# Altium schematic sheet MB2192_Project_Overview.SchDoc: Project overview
size A4; Date: Not used; ApprovedBy: Not used; CheckedBy: Not used; Author: Not used; CompanyName: STMicroelectronics; DrawnBy: Not used; Engineer: Not used; Organization: Not used; Address1: Not used; Address2: Not used; Address3: Not used; Address4: Not used; DocumentNumber: 1; Revision: Not used; SheetNumber: 1; SheetTotal: 17
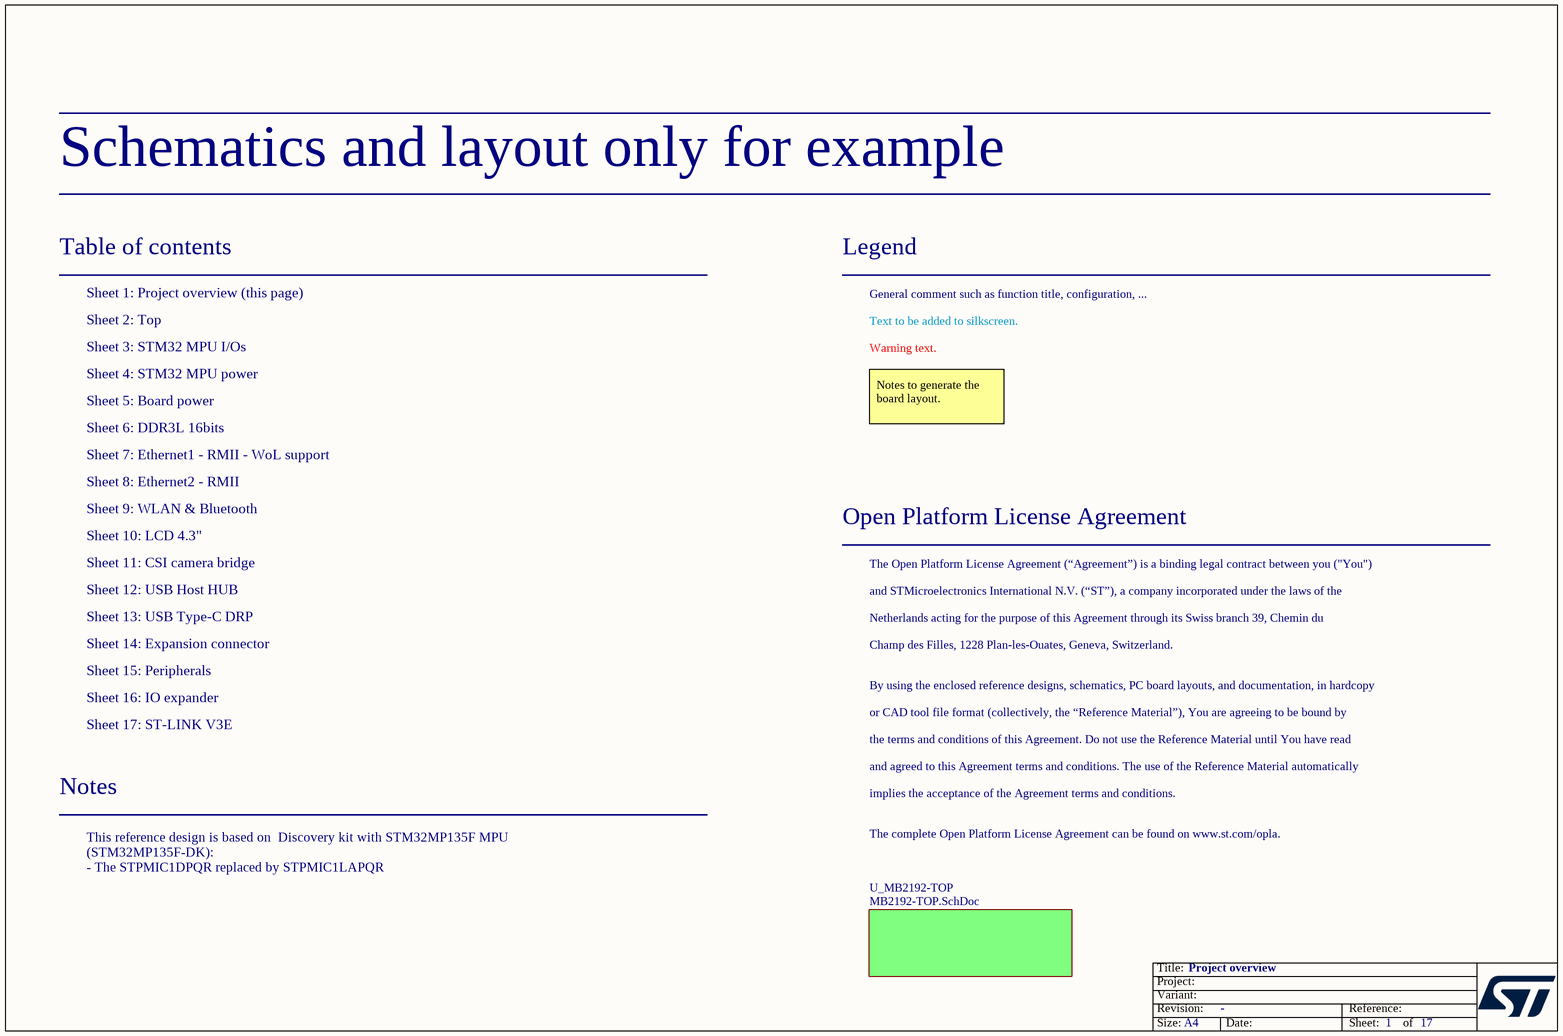
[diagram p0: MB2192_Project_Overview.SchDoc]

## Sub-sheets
U_MB2192-TOP = MB2192-TOP.SchDoc: no entries

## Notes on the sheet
- Schematics and layout only for example
- Table of contents
- Sheet 1: Project overview (this page)
- Legend
- General comment such as function title, configuration, ...
- Sheet 2: Top
- Sheet 3: STM32 MPU I/Os
- Sheet 4: STM32 MPU power
- Text to be added to silkscreen.
- Warning text.
- Sheet 6: DDR3L 16bits
- Sheet 5: Board power
- Notes to generate the board layout.
- Sheet 7: Ethernet1 - RMII - WoL support
- Sheet 8: Ethernet2 - RMII
- Sheet 9: WLAN & Bluetooth
- Sheet 10: LCD 4.3"
- Sheet 11: CSI camera bridge
- Open Platform License Agreement
- The Open Platform License Agreement (“Agreement”) is a binding legal contract between you ("You")
- Sheet 13: USB Type-C DRP
- Sheet 12: USB Host HUB
- Sheet 14: Expansion connector
- and STMicroelectronics International N.V. (“ST”), a company incorporated under the laws of the
- Netherlands acting for the purpose of this Agreement through its Swiss branch 39, Chemin du
- Champ des Filles, 1228 Plan-les-Ouates, Geneva, Switzerland.
- Sheet 15: Peripherals
- Sheet 16: IO expander
- By using the enclosed reference designs, schematics, PC board layouts, and documentation, in hardcopy
- or CAD tool file format (collectively, the “Reference Material”), You are agreeing to be bound by
- Sheet 17: ST-LINK V3E
- the terms and conditions of this Agreement. Do not use the Reference Material until You have read
- and agreed to this Agreement terms and conditions. The use of the Reference Material automatically
- Notes
- implies the acceptance of the Agreement terms and conditions.
- The complete Open Platform License Agreement can be found on www.st.com/opla.
- This reference design is based on  Discovery kit with STM32MP135F MPU (STM32MP135F-DK):
  - The STPMIC1DPQR replaced by STPMIC1LAPQR
  - It is applicable to STM32MP13xA and STM32MP13xC (CPU freq up to 650 MHz)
